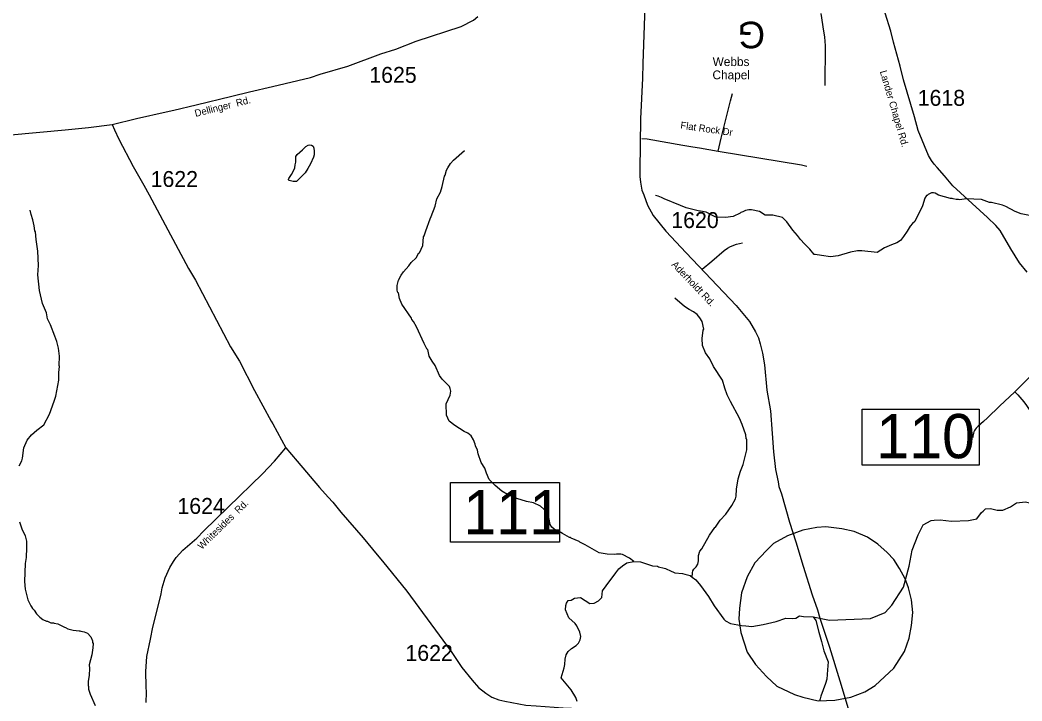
# Model space of a CAD drawing. Extents: x 1268485 to 1426702, y 514839 to 616766.
# Drawn here: x 1313854 to 1323145, y 604404 to 610720 of the extents above; entities that cross this region are included whole.
import ezdxf

# ---------------------------------------------------------------- set-up
doc = ezdxf.new("R2010")
doc.units = 0
for name, color, linetype in [('Old_Level_10', 7, 'Continuous'), ('Old_Level_11', 7, 'Continuous'), ('Old_Level_22', 7, 'Continuous'), ('Old_Level_3', 7, 'Continuous'), ('Old_Level_31', 7, 'Continuous'), ('Old_Level_32', 7, 'Continuous'), ('Old_Level_35', 7, 'Continuous'), ('Old_Level_50', 7, 'Continuous'), ('Old_Level_59', 7, 'Continuous'), ('Old_Level_62', 7, 'Continuous'), ('Old_Level_8', 7, 'Continuous')]:
    doc.layers.add(name, color=color, linetype=linetype)

msp = doc.modelspace()

# ---------------------------------------------------------------- linework, layer by layer
at = {"layer": 'Old_Level_22'}
msp.add_line((1320488.381, 610272.651), (1320488.381, 610272.651), dxfattribs=at)
at = {"layer": 'Old_Level_3'}
msp.add_lwpolyline([(1321254.053, 604405.938), (1321409.052, 604412.396), (1321557.594, 604438.23), (1321686.761, 604489.896), (1321783.636, 604548.021), (1321958.011, 604709.48), (1322054.886, 604864.48), (1322100.094, 604987.188), (1322119.469, 605103.438), (1322132.386, 605226.147), (1322119.469, 605342.396), (1322093.636, 605452.189), (1322061.344, 605536.147), (1322009.678, 605633.022), (1321958.011, 605716.98), (1321893.427, 605781.563), (1321809.469, 605859.064), (1321712.594, 605923.647), (1321589.886, 605975.313), (1321473.635, 606001.147), (1321325.094, 606020.522), (1321241.136, 606014.063), (1321111.969, 605988.23), (1320969.886, 605936.563), (1320840.719, 605865.522), (1320776.136, 605800.938), (1320666.344, 605684.688), (1320595.302, 605555.522), (1320543.636, 605406.979), (1320524.261, 605264.896), (1320517.802, 605161.563), (1320537.177, 605038.855), (1320595.302, 604858.021), (1320672.802, 604741.772), (1320776.136, 604631.98), (1320873.011, 604541.563), (1321034.469, 604464.063), (1321111.969, 604438.23), (1321254.053, 604405.938)], dxfattribs=at)
at = {"layer": 'Old_Level_31'}
msp.add_line((1321271.598, 605171.624), (1321271.598, 605171.624), dxfattribs=at)
for points in [[(1321661.979, 607110.543), (1322748.8, 607110.543), (1322748.8, 606592.385), (1321661.979, 606592.385), (1321661.979, 607110.543)], [(1317846.393, 606428.959), (1318857.113, 606428.959), (1318857.113, 605878.242), (1317846.393, 605878.242), (1317846.393, 606428.959)]]:
    msp.add_lwpolyline(points, dxfattribs=at)
at = {"layer": 'Old_Level_32'}
for points in [[(1323193.278, 608381.734), (1323122.293, 608466.498), (1323042.148, 608597.082), (1322941.394, 608768.903), (1322902.467, 608814.722), (1322824.612, 608888.032), (1322504.032, 609182.418), (1322426.177, 609274.056), (1322357.481, 609351.948), (1322330.003, 609381.73), (1322307.104, 609416.094), (1322277.336, 609464.204), (1322183.378, 609696.129), (1322146.739, 609822.131), (1322045.978, 610165.772), (1322015.534, 610292.701), (1321952.229, 610513.961), (1321927.497, 610616.595), (1321876.201, 610783.375), (1321842.904, 610928.792)], [(1319648.044, 610844.232), (1319629.495, 610316.671), (1319627.205, 610181.516), (1319606.596, 609803.542), (1319599.727, 609327.066), (1319602.017, 609269.797), (1319606.596, 609214.82), (1319620.335, 609141.515), (1319638.655, 609097.991), (1319673.003, 609001.78), (1319723.38, 608907.858), (1319842.452, 608761.25), (1320029.88, 608561.836), (1320493.961, 608073.649), (1320617.621, 607924.738), (1320672.581, 607828.518), (1320700.06, 607771.245), (1320718.38, 607716.262), (1320738.99, 607629.207), (1320756.11, 607521.951), (1320780.21, 607287.857), (1320813.356, 607095.87), (1320829.386, 606885.121), (1320841.453, 606714.881), (1320860.36, 606550.174), (1320883.259, 606435.627), (1320890.129, 606392.098), (1320915.32, 606325.661), (1320988.599, 606062.203), (1321048.139, 605881.218), (1321116.839, 605654.415), (1321199.278, 605388.666), (1321248.158, 605249.232), (1321271.505, 605171.505)], [(1314708.353, 609750.996), (1314934.588, 609805.238), (1315207.531, 609869.289), (1315278.517, 609885.324), (1315486.895, 609933.43), (1315816.636, 610012.69), (1315981.506, 610053.924), (1316194.464, 610102.03), (1316547.104, 610186.788), (1316636.408, 610216.567), (1316892.874, 610290.788), (1317199.717, 610405.326), (1317339.399, 610451.141), (1317527.168, 610524.445), (1317943.924, 610659.599), (1318057.254, 610718.7), (1318099.291, 610751.573)], [(1313329.048, 609612.461), (1313410.741, 609618.499), (1313766.756, 609656.355), (1314270.944, 609700.412), (1314489.628, 609724.719), (1314708.353, 609750.996)], [(1314708.353, 609750.996), (1314728.948, 609702.064), (1314770.576, 609613.817), (1314902.978, 609363.033), (1315001.408, 609187.371), (1315051.523, 609099.256), (1315199.01, 608820.842), (1315415.616, 608414.467), (1315480.158, 608308.121), (1315805.026, 607688.136), (1315889.435, 607555.127), (1316028.71, 607284.889), (1316183.667, 606998.931), (1316197.334, 606974.623), (1316317.307, 606752.816)], [(1315023.455, 604390.739), (1315025.244, 604482.065), (1315024.631, 604537.351), (1315021.484, 604676.892), (1315028.364, 604817.705), (1315062.533, 604977.223), (1315085.312, 605087.367), (1315134.668, 605284.866), (1315161.245, 605398.808), (1315172.634, 605451.981), (1315199.914, 605547.658), (1315242.119, 605642.663), (1315275.142, 605698.855), (1315301.205, 605733.446), (1315362.402, 605803.117), (1315492.307, 605915.344), (1315558.458, 605982.776), (1315783.137, 606202.08), (1316101.404, 606511.648), (1316212.521, 606629.759), (1316317.307, 606752.816)], [(1316317.307, 606752.816), (1316423.611, 606629.759), (1316631.664, 606385.164), (1316712.152, 606294.011), (1316753.156, 606247.827), (1316827.32, 606154.849), (1317034.104, 605918.155), (1317166.529, 605758.181), (1317215.124, 605701.97), (1317439.287, 605422.252), (1317851.434, 604864.118), (1317950.145, 604713.715), (1318047.28, 604596.053), (1318105.489, 604529.862), (1318174.281, 604476.908), (1318227.198, 604439.841), (1318293.965, 604415.339), (1318350.154, 604401.666), (1318545.3, 604365.204), (1318640.974, 604357.608), (1318890.789, 604340.896), (1319046.4, 604332.972)], [(1321271.505, 605171.505), (1321360.311, 604904.33), (1321456.491, 604590.471), (1321679.809, 603853.319), (1321897.358, 603174.055), (1321917.969, 603082.418), (1321927.128, 603004.526), (1321931.708, 602915.179), (1321931.708, 602816.669), (1321920.258, 602729.614), (1321897.358, 602617.357), (1321865.298, 602451.264), (1321833.239, 602297.771), (1321814.918, 602148.859), (1321814.918, 601832.71), (1321811.483, 601399.723), (1321823.396, 601307.962), (1321823.396, 601201.848), (1321810.86, 601098.629)]]:
    msp.add_lwpolyline(points, dxfattribs=at)
at = {"layer": 'Old_Level_35'}
for points in [[(1321279.141, 610779.26), (1321304.978, 610618.295), (1321312.872, 610562.725), (1321316.871, 610521.92), (1321319.536, 610483.37), (1321316.871, 610111.508)], [(1320326.162, 609504.605), (1320354.869, 609625.483), (1320443.246, 609969.612), (1320460.881, 610038.561)], [(1319618.527, 609622.254), (1319667.842, 609616.666), (1319998.796, 609560.789), (1320093.325, 609544.232), (1320155.763, 609533.21), (1320326.162, 609504.605)], [(1320326.162, 609504.605), (1321100.848, 609375.73), (1321148.83, 609364.452)], [(1320179.754, 608409.934), (1320267.517, 608483.856), (1320382.038, 608582.486), (1320415.359, 608604.734), (1320441.401, 608617.96), (1320498.098, 608639.747), (1320554.282, 608654.562)], [(1323760.886, 607936.264), (1323420.603, 607609.463), (1323284.345, 607478.485), (1323077.858, 607271.075)], [(1323077.858, 607271.075), (1322937.397, 607139.022), (1322825.951, 607031.113), (1322786.992, 606995.742), (1322739.214, 606951.553), (1322728.859, 606943.197), (1322719.324, 606933.714), (1322711.02, 606923.204), (1322704.048, 606911.824), (1322698.204, 606899.726), (1322693.898, 606887.064), (1322691.027, 606873.941), (1322689.592, 606860.613), (1322689.797, 606847.233)], [(1323077.858, 607271.075), (1323106.77, 607242.112), (1323161.724, 607179.212), (1323186.536, 607143.379), (1323210.117, 607106.726), (1323232.467, 607069.356), (1323253.588, 607031.318), (1323257.279, 607019.066), (1323259.329, 607006.455), (1323259.842, 606993.64), (1323258.714, 606980.926), (1323256.048, 606968.418), (1323251.64, 606956.372)]]:
    msp.add_lwpolyline(points, dxfattribs=at)
at = {"layer": 'Old_Level_50'}
msp.add_line((1321271.598, 605171.624), (1321271.598, 605171.624), dxfattribs=at)
at = {"layer": 'Old_Level_59'}
for points in [[(1322329.11, 606081.57), (1322386.462, 606085.573), (1322491.827, 606071.821), (1322649.876, 606078.697), (1322725.464, 606094.741), (1322768.986, 606152.039), (1322785.019, 606165.79), (1322807.925, 606186.418), (1322853.736, 606188.709), (1322913.291, 606174.958), (1322965.973, 606172.666), (1323036.981, 606204.753), (1323094.245, 606241.424), (1323178.996, 606250.592), (1323243.132, 606234.548), (1323302.686, 606202.461), (1323350.788, 606165.79), (1323421.795, 606131.411), (1323513.418, 606117.66), (1323630.236, 606145.163), (1323731.021, 606250.592), (1323804.319, 606416.298), (1323875.327, 606538.916)], [(1313848.669, 606064.754), (1313871.122, 606000.214), (1313901.675, 605935.52), (1313912.542, 605887.281), (1313913.055, 605823.357), (1313908.954, 605735.492), (1313899.624, 605679.768), (1313895.728, 605511.933), (1313902.085, 605439.858), (1313925.768, 605343.33), (1313952.425, 605286.735), (1313960.217, 605278.533), (1313967.907, 605262.334), (1313983.49, 605245.981), (1314006.764, 605213.429), (1314037.932, 605180.723), (1314063.461, 605160.116), (1314099.037, 605143.25), (1314107.034, 605143.045), (1314138.715, 605130.281), (1314162.706, 605129.716), (1314170.6, 605125.513), (1314202.486, 605120.746), (1314265.745, 605087.27), (1314273.742, 605087.065), (1314297.425, 605074.506), (1314345.1, 605061.331), (1314400.977, 605054.001), (1314408.974, 605055.795), (1314416.868, 605051.591), (1314448.754, 605046.824), (1314480.434, 605032.061), (1314509.654, 604999.406), (1314526.776, 604961.01), (1314526.366, 604945.016), (1314530.159, 604936.916), (1314529.237, 604896.982), (1314519.702, 604833.263), (1314493.558, 604737.964), (1314496.736, 604705.874), (1314495.3, 604641.949), (1314485.971, 604586.226), (1314485.048, 604546.292), (1314488.841, 604538.193), (1314488.226, 604514.202), (1314503.092, 604465.86), (1314548.717, 604360.823)], [(1321207.689, 605183.665), (1321359.919, 605154.651), (1321740.152, 605168.402), (1321875.296, 605225.7), (1321937.192, 605293.349), (1322045.994, 605459.514), (1322097.532, 605654.327), (1322126.164, 605803.303), (1322183.427, 605946.548), (1322229.238, 606038.225), (1322303.25, 606077.685), (1322329.11, 606081.57)], [(1319019.057, 604400.551), (1319007.882, 604436.794), (1318965.296, 604508.572), (1318872.134, 604617.498), (1318899.245, 604711.494), (1318907.099, 604743.091), (1318908.226, 604791.022), (1318917.146, 604830.75), (1318937.856, 604862.226), (1318968.512, 604889.498), (1319011.163, 604918.462), (1319031.668, 604939.941), (1319048.379, 604971.519), (1319053.198, 605003.353), (1319046.124, 605043.544), (1319015.469, 605102.239), (1318999.987, 605122.591), (1318942.282, 605174.169), (1318912.505, 605248.656), (1318913.65, 605288.765), (1318922.375, 605310.367), (1318936.556, 605334.603), (1318962.897, 605340.333), (1318993.82, 605357.523), (1319051.084, 605363.253), (1319138.295, 605307.138), (1319178.382, 605312.162), (1319216.83, 605333.18), (1319247.588, 605362.45), (1319256.089, 605425.135), (1319288.157, 605470.974), (1319379.779, 605592.446), (1319404.976, 605629.117), (1319441.624, 605656.62), (1319480.564, 605684.122), (1319544.195, 605697.557)], [(1319544.195, 605697.557), (1319607.249, 605693.507), (1319718.387, 605658.853), (1319766.267, 605653.676), (1319774.161, 605649.523), (1319826.439, 605635.992), (1319840.182, 605633.7), (1319851.635, 605626.824), (1319879.122, 605615.365), (1319924.933, 605592.446), (1319995.94, 605585.57), (1320018.846, 605580.986), (1320068.309, 605568.425), (1320087.891, 605551.713)], [(1320087.891, 605551.713), (1320119.264, 605527.21), (1320164.068, 605476.152), (1320237.682, 605374.446), (1320291.61, 605285.197), (1320378.757, 605163.191), (1320396.392, 605148.735), (1320441.708, 605121.668), (1320545.26, 605103.162), (1320585.245, 605102.188), (1320641.122, 605094.857), (1320745.493, 605114.337), (1320866.166, 605141.404), (1320954.851, 605171.239), (1321014.045, 605168.402), (1321048.403, 605172.986), (1321082.761, 605193.613), (1321119.41, 605186.737), (1321207.689, 605183.665)]]:
    msp.add_lwpolyline(points, dxfattribs=at)
at = {"layer": 'Old_Level_62'}
for points in [[(1316346.716, 609251.212), (1316371.835, 609288.532), (1316392.032, 609328.465), (1316401.875, 609349.996), (1316406.283, 609376.602), (1316409.872, 609400.183), (1316411.307, 609434.939), (1316412.435, 609453.599), (1316423.405, 609473.232), (1316448.217, 609495.634), (1316473.643, 609517.37), (1316504.196, 609545.872), (1316526.854, 609558.38), (1316541.925, 609562.994), (1316557.407, 609560.738), (1316571.453, 609549.204), (1316578.527, 609530.391), (1316579.757, 609503.631), (1316579.552, 609468.773), (1316573.401, 609446.575), (1316547.154, 609386.854), (1316523.061, 609341.435), (1316498.454, 609302.885), (1316462.878, 609268.282), (1316432.222, 609237.935), (1316416.331, 609223.376), (1316385.778, 609221.633), (1316361.685, 609227.221), (1316346.306, 609232.553), (1316342.717, 609240.088), (1316346.716, 609251.212)], [(1319544.195, 605697.557), (1319504.108, 605730.006), (1319440.849, 605761.533), (1319424.958, 605765.89), (1319384.972, 605766.865), (1319368.876, 605763.276), (1319297.005, 605765.019), (1319225.339, 605778.706), (1319095.029, 605853.807), (1319044.586, 605878.106), (1319039.767, 605883.129), (1318964.513, 605912.964), (1318956.619, 605919.116), (1318948.622, 605919.321), (1318885.466, 605956.846), (1318845.993, 605977.812), (1318822.207, 605986.373), (1318784.888, 606015.234), (1318769.509, 606041.583), (1318760.691, 606089.77), (1318738.238, 606158.258), (1318679.491, 606211.674), (1318616.232, 606241.201), (1318548.565, 606254.837), (1318461.213, 606280.93), (1318374.066, 606319.018), (1318322.803, 606350.238), (1318260.057, 606403.705), (1318205.41, 606459.018), (1318178.651, 606515.612), (1318163.785, 606561.954), (1318129.028, 606616.754), (1318102.987, 606697.339), (1318095.707, 606729.482), (1318078.688, 606769.877), (1318074.997, 606785.974), (1318057.978, 606826.317), (1318036.858, 606862.816), (1318005.485, 606889.576), (1317971.856, 606904.391), (1317885.119, 606958.422), (1317834.061, 606999.638), (1317807.404, 607056.283), (1317805.866, 607160.245), (1317843.698, 607239.292), (1317848.62, 607279.124), (1317843.186, 607303.268), (1317835.599, 607319.417), (1317820.015, 607337.769), (1317769.265, 607388.98), (1317741.993, 607421.635), (1317702.213, 607514.524), (1317675.146, 607555.175), (1317648.284, 607603.772), (1317633.725, 607664.109), (1317629.727, 607664.212), (1317601.019, 607720.857), (1317528.636, 607874.493), (1317501.774, 607923.141), (1317488.241, 607941.442), (1317484.55, 607955.539), (1317395.557, 608085.594), (1317372.796, 608138.138), (1317362.031, 608190.375), (1317356.085, 608192.477), (1317354.239, 608198.526), (1317350.753, 608218.621), (1317351.676, 608258.555), (1317362.749, 608306.281), (1317387.868, 608353.648), (1317408.578, 608385.123), (1317457.893, 608439.872), (1317480.654, 608471.297), (1317525.663, 608514.203), (1317552.627, 608559.212), (1317558.676, 608561.365), (1317588.306, 608628.622), (1317596.201, 608708.388), (1317602.352, 608718.23), (1317615.475, 608763.854), (1317658.024, 608874.788), (1317664.585, 608898.574), (1317702.828, 608993.615), (1317718.412, 609061.18), (1317751.835, 609124.336), (1317767.829, 609175.291), (1317789.36, 609271.358), (1317795.511, 609281.201), (1317808.635, 609326.825), (1317819.195, 609350.56), (1317844.109, 609389.93), (1317872.816, 609421.2), (1317974.932, 609510.706)], [(1319802.458, 609074.713), (1319770.778, 609087.478), (1319746.889, 609092.04)], [(1323214.115, 608908.211), (1323138.451, 608922.001), (1323082.984, 608945.377), (1322996.042, 608989.412), (1322964.362, 609002.177), (1322861.015, 609028.679), (1322845.021, 609029.089), (1322769.665, 609054.875), (1322625.821, 609062.359), (1322569.534, 609051.697), (1322555.693, 609056.054), (1322533.65, 609056.566), (1322505.763, 609061.282), (1322497.868, 609065.435), (1322481.874, 609065.845), (1322370.633, 609096.5), (1322339.055, 609113.263), (1322323.164, 609117.672), (1322307.17, 609118.031), (1322274.771, 609100.807), (1322266.569, 609093.015), (1322258.572, 609091.22), (1322244.629, 609066.87), (1322222.073, 608995.307), (1322150.305, 608850.899), (1322128.467, 608832.547), (1322107.962, 608809.068), (1322080.792, 608761.753), (1322047.676, 608712.591), (1322016.816, 608675.324), (1321984.315, 608652.153), (1321935.923, 608635.338), (1321870.409, 608606.016), (1321802.229, 608562.596), (1321658.59, 608578.077), (1321618.605, 608579.052), (1321554.321, 608566.594), (1321441.542, 608531.377), (1321369.364, 608525.123), (1321285.6, 608535.119), (1321225.93, 608546.551), (1321217.83, 608544.756), (1321178.973, 608593.661), (1321128.12, 608642.874), (1321091.108, 608683.731), (1321064.041, 608720.383), (1321019.238, 608771.441), (1320962.951, 608846.747), (1320923.991, 608889.654), (1320834.486, 608909.801), (1320762.512, 608911.544), (1320711.249, 608944.762), (1320635.585, 608958.603), (1320611.697, 608959.166), (1320579.503, 608951.99), (1320555.307, 608942.557), (1320539.108, 608934.97), (1320530.906, 608927.178), (1320466.212, 608898.728), (1320394.034, 608888.526), (1320322.06, 608890.218), (1320298.172, 608894.832), (1320215.126, 608936.816), (1320163.453, 608948.043), (1320155.353, 608946.248), (1320032.219, 608979.211), (1319976.65, 608998.536), (1319826.142, 609062.154), (1319802.458, 609074.713)], [(1313846.823, 606584.458), (1313869.994, 606631.877), (1313876.556, 606655.714), (1313888.756, 606751.371), (1313918.386, 606822.575), (1313959.602, 606873.582), (1314008.609, 606916.335), (1314073.816, 606966.727), (1314126.104, 607065.408), (1314170.908, 607184.236), (1314184.031, 607231.91), (1314213.046, 607380.009), (1314213.149, 607451.06), (1314218.48, 607506.885), (1314216.635, 607514.934), (1314220.633, 607602.799), (1314210.381, 607674.977), (1314193.874, 607739.363), (1314177.06, 607787.704), (1314135.434, 607892.691), (1314108.777, 607949.285), (1314098.115, 608005.521), (1314062.128, 608090.31), (1314034.959, 608210.931), (1314018.349, 608355.237), (1314024.398, 608442.999), (1314019.477, 608575.053), (1314002.048, 608683.423), (1313995.691, 608755.499), (1313991.898, 608763.598), (1313985.028, 608811.734), (1313972.315, 608868.021), (1313955.501, 608916.413), (1313948.427, 608956.552)], [(1320087.891, 605551.713), (1320088.814, 605593.903), (1320093.222, 605609.795), (1320101.629, 605625.584), (1320124.185, 605649.062), (1320138.744, 605672.694), (1320145.408, 605704.477), (1320144.588, 605752.459), (1320157.506, 605792.137), (1320176.063, 605815.667), (1320247.011, 605941.877), (1320296.634, 606014.363), (1320302.683, 606016.464), (1320345.641, 606080.287), (1320397.52, 606138.112), (1320453.396, 606216.697), (1320486.922, 606279.853), (1320493.484, 606303.691), (1320498.918, 606367.513), (1320513.169, 606463.119), (1320534.802, 606534.528), (1320560.331, 606597.889), (1320592.422, 606732.711), (1320593.857, 606832.931), (1320587.91, 606835.084), (1320585.963, 606839.133), (1320582.784, 606873.172), (1320551.001, 606969.905), (1320526.395, 607026.448), (1320442.016, 607180.391), (1320411.463, 607245.085), (1320388.907, 607305.626), (1320366.659, 607380.112), (1320285.664, 607505.962), (1320249.267, 607576.808), (1320210.615, 607633.71), (1320182.215, 607702.351), (1320178.934, 607767.199), (1320189.597, 607843.837), (1320193.8, 607853.987), (1320179.447, 607924.32), (1320158.224, 607958.769), (1320132.9, 607987.374), (1320099.476, 608012.185), (1320058.056, 608035.151), (1320014.79, 608064.217), (1319924.567, 608140.343)], [(1321207.689, 605183.665), (1321232.844, 605150.103), (1321261.476, 605041.237), (1321284.382, 604955.29), (1321307.287, 604869.343), (1321347.373, 604766.206), (1321341.646, 604691.718), (1321334.948, 604606.966), (1321324.08, 604567.289), (1321279.276, 604448.409), (1321274.663, 604424.572), (1321268.086, 604403.158)]]:
    msp.add_lwpolyline(points, dxfattribs=at)

# ---------------------------------------------------------------- texts
at = {"layer": 'Old_Level_10'}
msp.add_text('Flat Rock Dr', height=65.61666, rotation=351.8841583, dxfattribs=at).set_placement((1319974.35, 609713.432))
at = {"layer": 'Old_Level_11'}
for s, rotation, p in [('Lander Chapel Rd.', 286.3418389, (1321825.886, 610242.374)), ('Dellinger  Rd.', 14.0414083, (1315481.902, 609821.294)), ('Aderholdt Rd.', 313.5499111, (1319890.948, 608446.907)), ('Whitesides  Rd.', 44.3064167, (1315538.621, 605803.924))]:
    msp.add_text(s, height=65.61666, rotation=rotation, dxfattribs=at).set_placement(p)
at = {"layer": 'Old_Level_22'}
for s, height, rotation, p in [('G', 246.062, 178.6309417, (1320765.449, 610701.302)), ('Webbs', 82.0208, 0.0000167, (1320276.312, 610293.157)), ('Chapel', 82.0208, 0.0000194, (1320274.7, 610170.124))]:
    msp.add_text(s, height=height, rotation=rotation, dxfattribs=at).set_placement(p)
at = {"layer": 'Old_Level_31'}
for s, p in [('110', (1321793.785, 606655.694)), ('111', (1317964.767, 605950.209))]:
    msp.add_text(s, height=410.1042, dxfattribs=at).set_placement(p)
at = {"layer": 'Old_Level_8'}
for s, p in [('1625', (1317092.649, 610137.707)), ('1618', (1322177.889, 609924.399)), ('1622', (1315064.479, 609171.766)), ('1620', (1319893.225, 608790.683)), ('1624', (1315313.219, 606139.241)), ('1622', (1317427.56, 604775.822))]:
    msp.add_text(s, height=147.6375, dxfattribs=at).set_placement(p)

doc.saveas('drawing.dxf')
